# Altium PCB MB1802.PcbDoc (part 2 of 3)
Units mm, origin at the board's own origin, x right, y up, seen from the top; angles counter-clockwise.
Board outline 70 x 70 mm, 4 copper layers (Top Layer, Signal Layer 1, Signal Layer 2, Bottom Layer), stack 1.56 mm thick; 220 components, 159 nets, 974 pads, 563 vias.
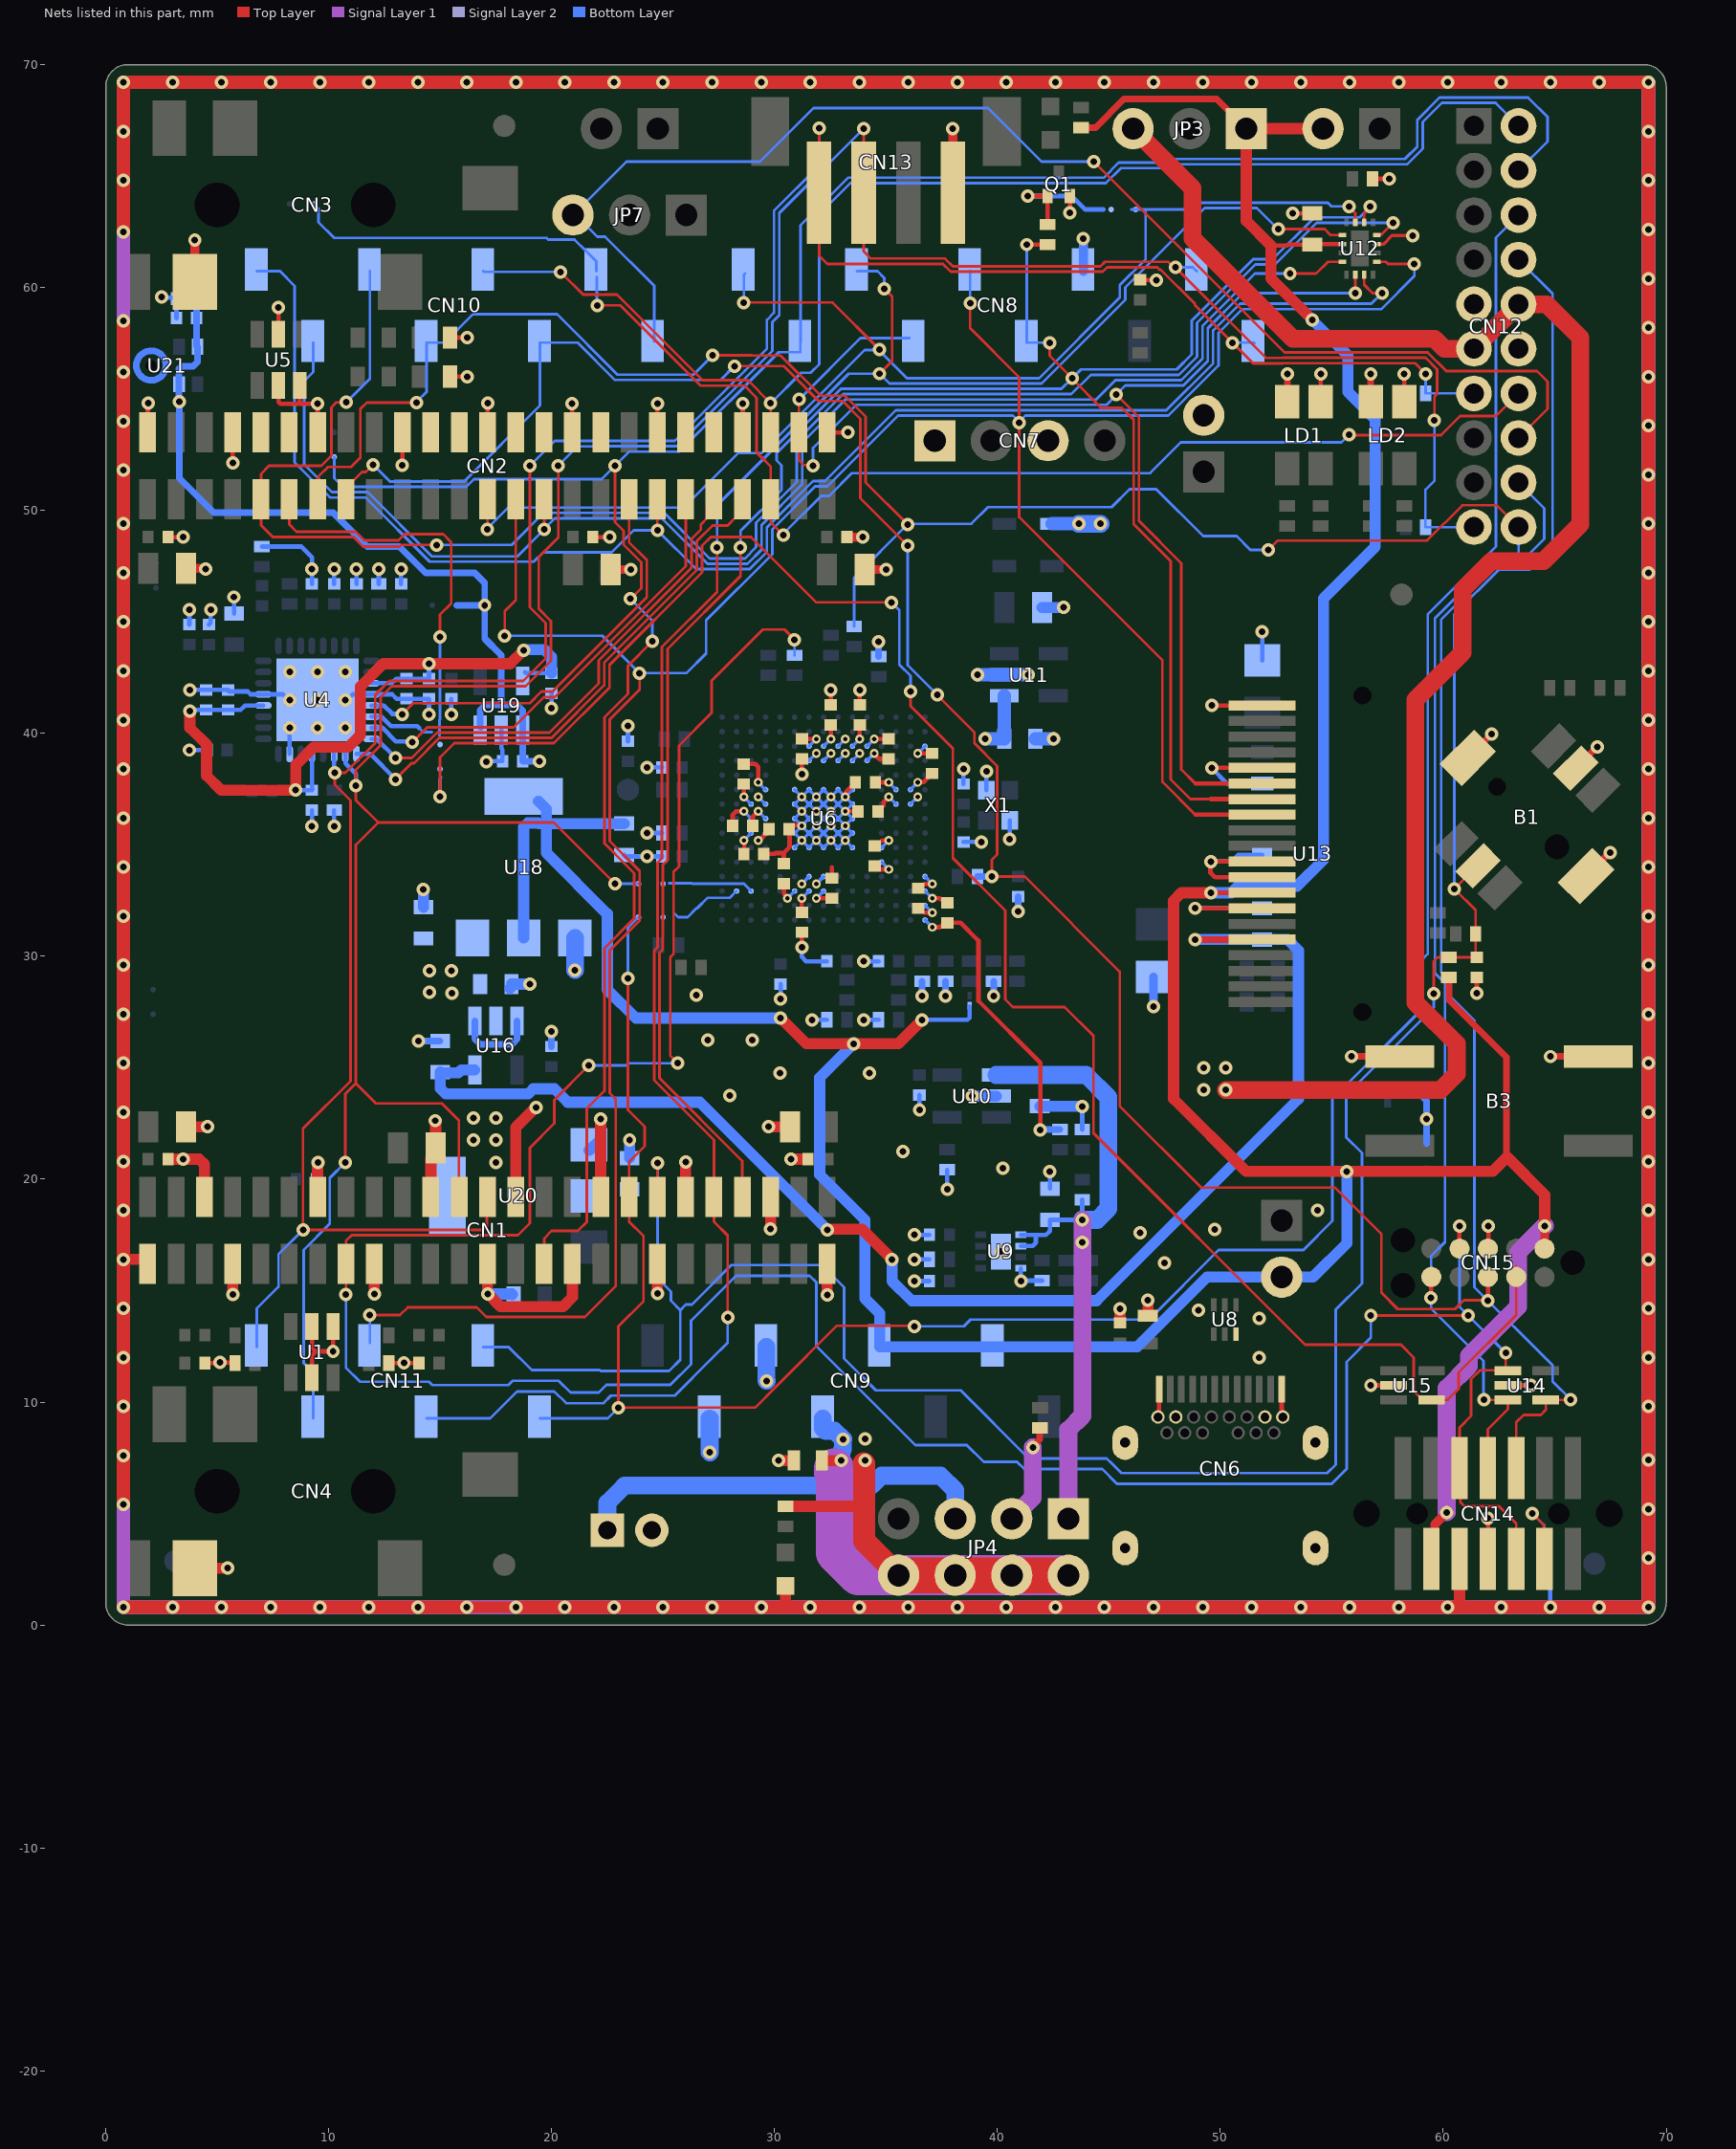
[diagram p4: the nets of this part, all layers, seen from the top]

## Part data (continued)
R48: library part MCD-00499, "Resistor,620R,0402,1%,1/16W", Manufacturer=YAGEO, Manufacturer_Part_Number=RC0402FR-07620RL, Package=R0402
R51 R52: library part MCD-00564, "Resistor,49R9,0603,1%,1/10W", Manufacturer=YAGEO, Manufacturer_Part_Number=RC0603FR-0749R9L, Package=R0603
R54: library part MCD-00057, "Resistor,2K2,0402,1%,1/16W", Manufacturer=YAGEO, Manufacturer_Part_Number=RC0402FR-072K2L, Package=R0402
R56: library part MCD-00419, "Resistor, 2K, 0402, +/-1%, 1/16W", Alternate_Manufacturer=N/A, Manufacturer=YAGEO, Manufacturer_Part_Number=RC0402FR-072KL, Package=0402
SB1 SB2 SB3 SB4 SB5 SB6 SB7 SB9 SB10: library part MCD-00071, "Solder Bridge ON"
SB8: library part MCD-00071, "Solder Bridge ON", Manufacturer=YAGEO, Manufacturer_Part_Number=RC0603JR-070RL, Package=SB0603
TP1: library part MCD-00074, "Test Point 1mm", Manufacturer=N/A
TP2: library part MCD-00630, "Test Point 0.3mm"
U1 U5: library part MCD-00247, "Quad Bidir ESD protection", Manufacturer=STMICROELECTRONICS, Manufacturer_HQ_COO=EU
U3: library part MCD-00170, "ESD protection 6V1", Manufacturer=STMICROELECTRONICS, Manufacturer_Part_Number=ESDALC6V1-1U2
U4: library part MCD-00265, "Low-Power, Stereo Codec with Headphone Amp", Manufacturer="CIRRUS LOGIC"
U6: library part MCD-02706, "MCU, Arm Cortex-M7 32-bit MCU, 512KB Flash, 276KB RAM, With Crypto", Manufacturer=STMICROELECTRONICS, Manufacturer_Part_Number=STM32F723IEK6, Package=BGA176
U7: library part MCD-01207, "High power Transient voltage suppressor:25V/35A EOS and ESD transients protection.", Manufacturer=STMICROELECTRONICS, Manufacturer_HQ_COO=EU, Manufacturer_Part_Number=ESDA25P35-1U1M, Package=QFN1610
U8: library part MCD-00649, "Common mode filter with ESD protection for USB 2.0 interface", Manufacturer=STMICROELECTRONICS, Manufacturer_HQ_COO=EU, Manufacturer_Part_Number=ECMF02-2AMX6
U9: library part MCD-02532, "IC, eFuse with Fast Overvoltage Protection 2.7V to 18V 4A 34mOhm 8-Pin WSON", Manufacturer="TEXAS INSTRUMENTS", Package=WSON8
U10: library part MCD-00159, "500mA, Enhanced single channel power switches with active high enable pin", Alternate_Manufacturer="TEXAS INSTRUMENTS", Alternate_Manufacturer_Part_Number=TPS2051C, Manufacturer=STMICROELECTRONICS
U11: library part MCD-02514, "LDO, 3.3V, 300mA, High input voltage: 2.5V to 28V, SOT23-5L", Manufacturer=STMICROELECTRONICS, Package=SOT23-5L
U12: library part MCD-00317, "Low voltage high bandwidth quad SPDT switch", Manufacturer=STMICROELECTRONICS
U13: library part MCD-01925, "128*64 Dots 20-pin OLED display", Manufacturer=RITDISPLAY, Manufacturer_Part_Number=9OL9935718000, Package=SMT
U14 U15: library part MCD-00136, "Dual Transil array for ESD protection", Manufacturer=STMICROELECTRONICS, Manufacturer_HQ_COO=EU
U16: library part MCD-01030, "LDO VOLTAGE REGULATOR, 3.6V, 150mA, 5-SOT-23, FULL REEL", Manufacturer="TEXAS INSTRUMENTS", Package=REG_SOT23-5L
U17: library part MCD-01026, "High power transient voltage suppressor", Manufacturer=STMICROELECTRONICS, Manufacturer_Part_Number=ESDA7P120-1U1M, Package=QFN1610
U18: library part MCD-00089, "LOW DROP FIXED AND ADJUSTABLE POSITIVE VOLTAGE REGULATORS (3.3 Volts)", Manufacturer=STMICROELECTRONICS
U19: library part MCD-00078, "Ultra low drop-low noise BiCMOS voltage, regulators low ESR capacitors compatible", Manufacturer=STMICROELECTRONICS
U20: library part MCD-00088, "IC REG LDO 5V 0.8A SOT223", Manufacturer=STMICROELECTRONICS
U21: library part MCD-02122, "MEMS sensors , omnidirectionnal digital microphone", Alternate_Manufacturer=N/A, Manufacturer=STMICROELECTRONICS, Manufacturer_Part_Number=MP23DB01HPTR, Package="RHLGA 5"
X1: library part MCD-01036, "Crystal, 24MHz, 6pF, +/-20ppm, 80R, 2x1.6mm", Manufacturer=NDK, Manufacturer_Part_Number=NX2016SA-24MHZ-EXS00A-CS10820, Package=2x1.6mm

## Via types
v1: diameter 0.6, hole 0.3, Top Layer to Bottom Layer, 509 vias
v2: diameter 0.4, hole 0.2, Top Layer to Bottom Layer, tented both sides, 54 vias

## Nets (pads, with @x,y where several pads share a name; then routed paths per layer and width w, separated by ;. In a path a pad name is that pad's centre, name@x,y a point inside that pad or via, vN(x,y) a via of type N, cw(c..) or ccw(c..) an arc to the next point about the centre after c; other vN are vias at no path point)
1V8: C16.2 C17.2 C18.2 C19.2 C20.2 C86.2 TP2.1 U4.5 U4.12 U4.27 U19.5 | length 34.6
  Top Layer w0.5: v1(3.775,40.99) 3.775,40.25 4.525,39.5 4.525,38.102 5.177,37.45 v1(8.525,37.45) 8.525,38.575 9.325,39.375 10.875,39.375 11.415,39.915 11.415,39.967 11.42,39.972 11.42,42.095 12.45,43.125 v1(14.5,43.125) 18.15,43.125 v1(18.75,43.725)
  Bottom Layer w0.2: v1(3.775,40.99) 3.835,41.05 C18.2@4.5,41.05 C19.2@5.5,41.05 6.05,41.05 6.25,41.25 U4.12@7.075,41.25 ; v1(8.525,37.45) C20.2@9.25,37.45 ; U4.5@9.255,39.125 9.255,37.52 C20.2@9.275,37.5 ; U4.27@11.925,42.25 12.825,42.25 13.025,42.45 C17.2@13.5,42.45 14.475,42.45 14.5,42.475 v1(14.5,43.125) ; U19.5@18.8,42.75 18.85,42.7 C86.2@20,42.7
  Bottom Layer w0.5: TP2.1@18.75,43.75 19.675,43.75 20,43.425 C86.2@20,42.7
3V3: C33.2 C34.1 C70.2 C74.1 C80.2 C85.2 CN9.2 CN9.4 CN14.3 CN15.1 JP2.2 JP3.1 JP5.2 LNK1.1 R41.1 R56.1 SB8.1 U12.2 U13.8 U18.2 U18.4 U19.1 U19.3 U21.2 U21.5 | length 233.6
  Top Layer w0.2: v1(49.575,32.85) U13.8@51.875,32.85 ; 52.26,61.89 52.275,61.875 53,61.875 53.05,61.925 C70.2@54.125,61.925 ; C70.2@54.125,61.95 U12.2@55.475,61.95
  Top Layer w0.3: R41.1@43.75,67.175 44.4,67.175 45.675,68.45 49.84,68.45 JP3.1@51.165,67.125 ; R56.1@60.25,29.05 60.25,28.05 62.825,25.475 62.825,21.025
  Top Layer w0.4: CN14.3@59.46,2.968 59.613,3.121 59.613,4.513 v1(60.15,5.05) ; CN15.1@64.54,16.885 64.55,16.895 v1(64.55,17.9)
  Top Layer w0.5: v1@30.294,27.206 31.425,26.075 v1(33.55,26.075) 35.55,26.075 v1(36.625,27.15) v1@36.65,27.175 ; v1(49.575,32.85) 48.25,32.85 47.9,32.5 47.9,23.6 51.15,20.35 62.22,20.35 62.86,20.99 64.55,19.3 v1(64.55,17.9) ; v1(54.125,58.545) 52.26,60.41 52.26,61.89 51.165,62.985 JP3.1@51.165,67.125 JP2.2@54.605,67.125
  Signal Layer 1 w0.8: v1(60.15,5.05) 60.15,10.625 61.15,11.625 61.15,12.075 63.35,14.275 63.35,16.7 v1(64.55,17.9)
  Bottom Layer w0.2: v1(36.625,27.15) 38.656,27.15 38.75,27.244 LNK1.1@38.75,27.75
  Bottom Layer w0.3: C33.2@4.075,59.5 C34.1@4.075,58.625 4.075,57.377 U21.5@4.114,57.338 4.114,56.664 3.925,56.475 3.415,56.475 3.292,56.352 U21.2@3.292,55.662 3.292,54.883 v1(3.3,54.875) 3.3,51.45 4.85,49.9 10.2,49.9 11.725,48.375 13.175,48.375 14.35,47.2 16.55,47.2 17,46.75 v1(17,45.75) ; SB8.1@15.75,45.75 v1(17,45.75) ; U19.3@16.825,40.275 16.8,40.3 16.8,41.05 17.025,41.275 17.738,41.275 ; U19.1@18.675,39.9 18.7,39.875 C85.2@18.7,38.75 v1(19.45,38.75) ; U19.1@18.7,40.15 18.7,41.025 18.45,41.275 17.738,41.275 ; v1(17,45.75) 17,44.25 17.738,43.512 17.738,41.275
  Bottom Layer w0.5: U18.2@18.75,30.825 18.75,35.798 18.932,35.98 19.383,35.98 19.413,35.95 19.763,35.95 ; U18.4@19.413,36.95 19.763,36.6 19.763,35.95 ; C80.2@23.25,35.95 19.763,35.95 ; v1(30.275,27.225) 23.775,27.225 22.5,28.5 22.5,31.9 19.763,34.637 19.763,35.95 ; v1(33.55,26.075) 32.025,24.55 32.025,20.2 34.05,18.175 34.05,14.65 34.725,13.975 34.714,13.964 34.714,12.472 39.794,12.472 46.272,12.472 49.405,15.605 JP5.2@52.75,15.605 54.155,15.605 55.675,17.125 v1(55.675,20.35) ; v1(49.575,32.85) 50.5,32.85 50.8,33.15 C74.1@51.875,33.15 53.45,33.15 54.625,34.325 54.625,46.05 56.95,48.375 56.95,54.1 55.725,55.325 55.725,56.945 v1@54.144,58.526
3V3_STLK: C50.1 C51.1 C52.1 C53.1 C54.1 C55.1 C56.1 C57.1 C58.1 C60.2 C61.1 C62.1 C63.1 C64.1 C65.1 C66.1 C67.1 C68.1 CN7.1 LD1.4 LD2.4 R28.2 R39.1 U6.C1 U6.C5 U6.C6 U6.C7 U6.C8 U6.C9 U6.F3 U6.G3 U6.G13 U6.H13 U6.J12 U6.J13 U6.K4 U6.N8 U6.N9 U6.N10 U6.P1 U6.R1 U11.1 | length 37.9
  Top Layer w0.2: C55.1@28.125,35.85 28.125,36.35 28.275,36.5 v2@28.6,36.5 ; v2(28.625,35.2) 28.65,35.175 C54.1@28.65,34.75 ; C56.1@28.625,37.725 28.625,37.175 v2@28.65,37.15 ; v2@29.275,35.225 29.35,35.225 29.595,35.47 29.62,35.47 29.775,35.625 C51.1@29.775,35.65 ; C53.1@30.425,33.225 30.425,32.786 30.575,32.636 v2(30.575,32.6) ; C52.1@31.225,31.975 31.225,32.45 v2@31.325,32.55 ; C57.1@31.225,39.75 31.825,39.75 v2@31.85,39.775 ; v2(31.875,32.6) C50.1@32.575,32.6 ; C58.1@32.525,40.375 32.525,39.775 v2@32.55,39.75 ; C61.1@33.825,40.375 33.825,39.725 v2@33.85,39.7 ; v2(34.475,39.75) 35.025,39.75 C62.1@35.1,39.825 ; C63.1@34.525,37.8 34.95,37.8 v2@35.05,37.7 ; C65.1@34.55,34.95 34.575,34.95 34.73,35.105 34.73,35.106 34.824,35.2 v2(35.125,35.2) ; C64.1@34.65,36.5 34.65,36.525 34.889,36.764 34.889,36.914 v2(35.125,37.15) ; v2@36.475,39.075 36.5,39.1 C68.1@37.075,39.1 ; C66.1@36.5,32.15 36.525,32.15 36.725,31.95 v2@37.025,31.95 ; v2(37.075,31.3) 37.425,31.3 37.625,31.5 37.65,31.5 38.35,31.5 39.15,30.7 39.15,28 41.925,25.225 v1(41.925,22.2)
  Top Layer w0.3: LD1.4@53,54.875 v1(53,56.125) ; LD2.4@56.75,54.875 v1(56.75,56.125)
  Bottom Layer w0.15: v2(28.625,35.2) U6.J13@28.95,35.525 ; v2(28.625,36.5) U6.H13@28.95,36.175 ; v2(28.625,37.15) U6.G13@28.95,36.825 ; v2(29.275,35.2) U6.J12@29.6,35.525 ; v2(30.575,32.6) U6.N10@30.9,32.925 ; v2(31.225,32.6) U6.N9@31.55,32.925 ; U6.C9@31.55,39.425 v2(31.875,39.75) ; v2(31.875,32.6) U6.N8@32.2,32.925 ; U6.C8@32.2,39.425 v2(32.525,39.75) ; U6.C7@32.85,39.425 v2(33.175,39.75) ; U6.C6@33.5,39.425 v2(33.825,39.75) ; U6.C5@34.15,39.425 v2(34.475,39.75) ; U6.K4@34.8,34.875 v2(35.125,35.2) ; v2(35.125,37.15) U6.G3@35.45,36.825 ; v2(35.125,37.8) U6.F3@35.45,37.475 ; v2(36.425,39.1) U6.C1@36.75,39.425 ; U6.R1@36.75,31.625 v2(37.075,31.3) ; U6.P1@36.75,32.275 v2(37.075,31.95)
  Bottom Layer w0.3: R28.2@34.675,43.45 v1(34.675,44.105) ; v1(41.925,22.2) 41.95,22.225 R39.1@42.8,22.225
  Bottom Layer w0.6: v1(39.45,39.75) C60.2@40.305,39.75 ; C60.2@40.275,39.775 40.305,39.805 U11.1@40.305,41.675
3V6: C75.1 C77.1 U13.5 U16.5 | length 63.8
  Top Layer w0.3: v1(48.875,30.75) U13.5@51.875,30.75
  Top Layer w0.5: v1(32.375,17.725) 32.4,17.75 33.925,17.75 v1(35.275,16.4)
  Bottom Layer w0.5: U16.5@16.55,24.9 15.95,24.9 15.825,24.775 15.025,24.775 C77.1@15,24.8 15,24.075 15.25,23.825 18.952,23.825 19.177,24.05 20.125,24.05 20.725,23.45 26.65,23.45 v1(32.375,17.725) ; v1(35.275,16.4) 35.275,15.425 36.15,14.55 44.45,14.55 53.5,23.6 53.5,30.268 53.018,30.75 C75.1@51.875,30.75 v1(48.875,30.75)
5V: C78.1 C81.2 CN9.5 CN12.6 CN12.15 JP3.3 JP4.2 JP4.4 JP4.6 JP4.8 R22.2 R48.2 U16.1 U16.3 U17.1 U18.3 | length 116.2
  Top Layer w0.5: R48.2@30.5,5.325 33.965,5.325 34.02,5.27 ; U17.1@32.125,7.375 v1(33,7.375)
  Top Layer w0.8: JP3.3@46.085,67.125 48.75,64.46 48.75,62.2 53.25,57.7 59.6,57.7 60.05,57.25 CN12.6@61.375,57.25 CN12.15@63.375,59.25 64.65,59.25 66.15,57.75 66.15,49.375 64.5,47.725 62.15,47.725 60.875,46.45 60.875,43.625 58.75,41.5 58.75,27.925 60.6,26.075 60.6,24.725 59.875,24 v1(50.25,24)
  Top Layer w1: v1@34,7.25 34.02,7.23 34.02,6.38 ; JP4.8@35.565,2.23 34.02,3.775 34.02,5.27 ; 34.02,5.27 34.025,5.275 34.025,6.375 34.02,6.38 ; 34.02,5.27 34.02,6.38
  Top Layer w1.6: JP4.8@35.565,2.23 JP4.6@38.105,2.23 JP4.4@40.645,2.23 JP4.2@43.185,2.23
  Signal Layer 1 w1.8: 32.68,7.03 32.68,6.845 32.75,6.775 32.75,3.25 33.77,2.23 JP4.8@35.52,2.23 ; JP4.8@35.5,2.25 JP4.8@35.52,2.23 ; JP4.6@38,2.25 JP4.6@38.02,2.23 ; JP4.4@40.645,2.23 JP4.6@38.105,2.23 JP4.6@38.02,2.23 ; JP4.4@40.75,2.25 40.75,2.24 40.76,2.23 JP4.2@43.185,2.23 ; JP4.8@35.52,2.23 JP4.8@35.565,2.23 JP4.6@38.02,2.23
  Bottom Layer w0.3: U16.1@16.55,27.1 16.55,26.3 16.8,26.05 18.225,26.05 18.45,26.275 U16.3@18.45,27.1 ; v1(36.625,28.22) R22.2@36.625,28.875
  Bottom Layer w0.8: CN9.5@32.174,9.267 32.174,8.824 32.284,8.714 32.686,8.714 33.068,8.332 v1(33.084,8.332) ; v1(33,7.375) 33,7.813 33.075,7.888 v1@33.075,8.325
  other v1: 34.075,7.375 34.075,8.35 49.25,24 49.25,25 50.25,25 15.525,28.35 14.525,28.375 14.525,29.35 15.5,29.35
5V_EXT: CN16.1 JP4.5 | length 19.1
  Bottom Layer w0.8: CN16.1@22.45,4.25 22.45,4.075 CN16.1@22.475,4.05 ; CN16.1@22.5,4.25 22.5,5.475 23.275,6.25 34.35,6.25 34.8,6.7 37.45,6.7 38.105,6.045 JP4.5@38.105,4.77
5V_STLK: C43.2 C47.2 JP4.1 R29.1 U9.5 U9.6 U10.1 | length 30.7
  Signal Layer 1 w0.8: JP4.1@43.185,4.77 43.185,8.76 43.819,9.394 43.819,17.272 v1@43.819,18.175
  Bottom Layer w0.2: U9.6@41.05,17 41.575,17 41.725,17.15 41.725,17.5 ; U9.5@41.05,17.5 41.725,17.5 ; C43.2@42.35,18.175 42.35,17.675 42.175,17.5 41.725,17.5 ; C43.2@42.355,18.175 v1(43.8,18.175) ; v1@43.805,18.28 R29.1@43.805,19.075
  Bottom Layer w0.8: U10.1@39.95,24.675 C47.2@41.9,24.675 43.975,24.675 44.975,23.675 44.975,18.675 44.475,18.175 v1(43.8,18.175)
  other v1: 43.8,17.175
5V_VIN: C84.2 D2.1 JP4.3 R43.2 U20.2 U20.4 | length 6.7
  Top Layer w0.3: v1(41.586,7.968) 41.586,8.011 41.9,8.325 R43.2@41.9,8.817
  Signal Layer 1 w0.8: JP4.3@40.645,4.77 41.586,5.711 v1(41.586,7.968)
  Bottom Layer w0.6: D2.1@42.445,49.4 v1(43.65,49.4)
  Bottom Layer w0.8: v1(43.65,49.4) v1(44.625,49.4)
  other v1: 17.5,20.75 16.5,21.75 17.5,21.75 16.5,22.75 17.5,22.75
ARD.D0_RX: CN2.37 CN10.1 U12.7 | length 71.3
  Top Layer w0.12: v1(24.745,49.105) CN2.37@24.745,50.5 ; U12.7@56.45,60.575 56.45,60.125 56.825,59.75 v1(57.25,59.75)
  Bottom Layer w0.12: CN10.1@6.774,60.73 7.82,60.73 8.475,60.075 8.475,52.15 9.805,50.82 9.816,50.82 10.056,50.58 11.656,50.58 14.536,47.7 19.2,47.7 19.625,48.125 22.7,48.125 23.68,49.105 v1(24.745,49.105) 26.485,47.365 28.886,47.365 29.66,48.139 29.66,49.249 31.726,51.315 32.265,51.315 35.445,54.495 47.57,54.495 49.675,56.6 49.675,58.071 50.879,59.275 55.846,59.275 55.851,59.27 56.77,59.27 v1(57.25,59.75)
ARD.D1_TX: CN2.29 CN10.2 U12.4 | length 65
  Top Layer w0.12: CN2.29@19.665,50.5 19.665,49.16 v1(19.675,49.15) ; v1(53.125,60.625) 54.3,60.625 54.825,61.15 U12.4@55.475,61.15
  Bottom Layer w0.12: CN10.2@9.314,57.525 9.314,56.211 8.9,55.797 8.9,52.075 10.15,50.825 10.536,50.825 10.541,50.82 11.755,50.82 14.635,47.94 18.465,47.94 v1(19.675,49.15) ; v1@19.675,49.175 20.15,49.65 24.95,49.65 26.995,47.605 28.787,47.605 29.42,48.238 29.42,49.349 31.24,51.169 31.24,53.032 33.183,54.975 44.425,54.975 45.295,55.845 48.241,55.845 49.195,56.799 49.195,58.27 51.55,60.625 v1(53.125,60.625)
ARD.D2_IO: CN2.9 CN10.3 U12.12 | length 77.5
  Top Layer w0.12: v1@10.775,54.85 10.35,54.85 10.125,54.625 10.125,52.45 9.675,52 7.325,52 6.965,51.64 CN2.9@6.965,50.5 6.965,49.335 7.495,48.805 11.12,48.805 11.548,48.378 13.192,48.378 13.264,48.45 v1(14.85,48.45) ; U12.12@57.025,62.35 57.065,62.39 57.24,62.39 v1(57.75,62.9)
  Bottom Layer w0.12: v1(10.8,54.85) 11.854,55.904 CN10.3@11.854,60.73 ; v1(14.85,48.45) 18.2,48.45 19.625,49.875 ; 19.625,49.89 25.049,49.89 27.094,47.845 28.674,47.845 29.18,48.351 29.18,49.448 31,51.268 31,53.132 33.083,55.215 43.315,55.215 44.185,56.085 48.142,56.085 48.955,56.898 48.955,58.417 51.573,61.035 52.449,61.035 54.314,62.9 v1(57.75,62.9)
ARD.D3_TIM: CN2.13 CN10.4 CN12.20 CN14.8 CN15.6 R17.2 U14.3 | length 123.5
  Top Layer w0.12: CN2.13@9.505,50.5 9.55,50.545 9.55,51.525 9.975,51.95 11,51.95 11.425,52.375 11.425,54.55 11.715,54.84 v1(13.95,54.84) ; v1(27.225,56.955) 28.975,56.955 ; 28.975,56.95 30.275,56.95 32.075,55.15 33.15,55.15 34.09,54.21 34.09,51.26 v1(35.975,49.375) ; v1(52.15,48.225) 52.575,48.65 59.275,48.65 60.855,50.23 62.395,50.23 CN12.20@63.375,49.25 ; v1(61.825,10.1) U14.3@62.9,10.1 62.9,9.675 62,8.775 CN14.8@62,7.032
  Top Layer w0.2: v1(59.45,14.675) 59.46,14.685 CN15.6@59.46,15.6
  Bottom Layer w0.12: v1@13.95,54.875 14.394,55.319 14.394,57.525 15.2,57.525 16.475,58.8 20.25,58.8 22.96,56.09 26.36,56.09 v1@27.22,56.95 ; R17.2@33.575,44.8 33.575,46.975 v1@36,49.4 ; v1(35.975,49.375) v1@36,49.4 ; v1(52.15,48.225) 51.346,48.225 50.726,48.845 49.226,48.845 47.116,50.955 45.93,50.955 45.125,50.15 39.575,50.15 38.825,49.4 v1@36,49.4 ; v1@61.8,10.1 61.8,11.85 59.45,14.2 v1(59.45,14.675) 59.45,16.55 60.075,17.175 60.075,28.8 59.625,29.25 59.625,45.154 62.301,47.83 63.13,47.83 63.375,48.075 CN12.20@63.375,49.25
ARD.D4_INT: CN2.46 CN10.5 CN12.11 | length 60.9
  Top Layer w0.12: v1@20.45,60.65 21.42,59.68 22.249,59.68 22.254,59.675 22.35,59.675 22.355,59.68 22.934,59.68 26.774,55.84 28.805,55.84 v1(29.825,54.82) 29.825,53.55 CN2.46@29.75,53.475
  Bottom Layer w0.12: CN10.5@16.934,60.73 16.964,60.7 v1(20.4,60.7) ; v1@29.825,54.8 31.2,56.175 31.625,56.175 32,56.55 32,63.286 33.399,64.684 44.863,64.684 45.538,65.359 47.334,65.359 47.5,65.525 58.375,65.525 59.075,66.225 59.075,67.425 59.93,68.28 62.345,68.28 CN12.11@63.375,67.25
ARD.D5_TIM: CN2.15 CN10.6 CN12.19 CN14.10 CN15.8 R19.2 U14.4 | length 142.6
  Top Layer w0.12: CN2.15@10.775,50.5 10.775,51.025 11.09,51.34 11.115,51.34 11.5,51.725 11.675,51.725 v1(12,52.05) ; v1(28.2,56.475) 30.411,56.475 30.818,56.068 31.976,54.91 33.051,54.91 33.85,54.111 33.85,50.54 v1(35.975,48.415) ; v1(37.3,41.725) 37.275,41.725 38.97,40.03 38.97,39.551 39.985,38.536 39.985,34.56 39.745,34.32 39.745,33.58 39.75,33.575 v1(39.755,33.575) 41.225,33.575 45.485,29.315 45.485,23.276 49.136,19.625 55.125,19.625 57.225,17.525 57.225,14.9 57.95,14.175 60.525,14.175 60.925,14.575 61.975,14.575 v1(62,14.55) ; CN14.10@63.27,7.032 63.27,9.095 63.6,9.425 64.375,9.425 64.6,9.65 U14.4@64.6,10.075 ; U14.4@64.6,10.1 v1(65.7,10.1)
  Top Layer w0.2: v1(62,14.55) CN15.8@62,15.615
  Bottom Layer w0.12: v1(12,52.05) 12.75,51.3 16.075,51.3 19.475,54.7 19.475,55.85 19.474,57.525 21.175,57.525 22.85,55.85 27.575,55.85 v1(28.2,56.475) ; v1(35.975,48.415) 35.975,43.05 v1(37.3,41.725) ; CN12.19@63.375,51.25 64.525,50.1 64.525,48.725 63.39,47.59 62.401,47.59 59.9,45.089 59.9,29.314 60.315,28.899 60.315,28.199 61.4,27.114 61.4,15.15 64.9,11.65 64.9,10.925 v1@65.7,10.125
  Bottom Layer w0.3: R19.2@39.1,33.575 v1(39.755,33.575)
ARD.D6_TIM: CN2.45 CN10.7 CN12.17 SB3.2 | length 67
  Top Layer w0.12: v1(22.05,59.2) 23.075,59.2 26.675,55.6 28.65,55.6 29.2,55.05 29.2,52.6 29.27,52.53 29.27,52.525 29.375,52.42 29.38,52.42 29.825,51.975 29.825,49.475 v1(30.4,48.9) ; v1(55.764,53.389) 55.779,53.375 59.9,53.375 60.755,54.23 62.355,54.23 CN12.17@63.375,55.25
  Bottom Layer w0.12: SB3.2@9.35,63.75 9.55,63.55 9.55,62.925 10.25,62.225 19.775,62.225 19.85,62.15 20.497,62.15 20.502,62.145 21.03,62.145 21.552,61.623 21.564,61.623 22.014,61.173 CN10.7@22.014,60.73 ; CN10.7@22.025,60.475 22.025,59.225 v1(22.05,59.2) ; v1(30.4,48.9) 30.4,48.95 32.1,50.65 32.45,50.65 33.475,51.675 46.85,51.675 48.225,53.05 55.425,53.05 v1(55.764,53.389)
ARD.D7_IO: CN10.8 CN12.18 JP7.3 | length 61.3
  Top Layer w0.12: v1(44.325,65.644) 52.879,57.09 59.299,57.09 60.139,56.25 64.2,56.25 64.675,55.775 64.675,54.55 CN12.18@63.375,53.25
  Bottom Layer w0.12: CN10.8@24.6,57.575 24.6,60.078 22.403,62.275 22.048,62.275 21.073,63.25 JP7.3@20.96,63.25 23.36,65.65 29.35,65.65 31.75,68.05 39.575,68.05 41.981,65.644 v1(44.325,65.644)
ARD.D8_IO: CN2.25 CN8.1 SB2.1 U12.15 | length 58.6
  Top Layer w0.12: v1(17.125,49.15) CN2.25@17.125,50.5 ; v1(28.625,59.325) 32.6,59.325 v1(34.7,57.225) ; v1(55.764,63.639) 55.764,63.611 56.05,63.325 U12.15@56.05,62.925
  Bottom Layer w0.12: v1(17.125,49.15) 17.125,49.2 18.055,50.13 25.93,50.13 28.375,52.575 29.425,52.575 34.05,57.2 v1@34.675,57.2 ; v1(28.625,59.325) 28.625,60.575 CN8.1@28.675,60.625 ; v1@34.7,57.175 35.94,55.935 41.875,55.935 45.49,59.55 45.49,60.104 46.65,61.264 46.65,63.5 ; 46,63.5 SB2.1@46.2,63.5 46.65,63.5 ; v1(55.764,63.639) 54.986,63.639 54.82,63.805 48.7,63.805 48.395,63.5 46.65,63.5
ARD.D9_TIM: CN1.29 CN8.2 CN12.12 SB4.2 | length 110.8
  Top Layer w0.12: CN1.29@19.665,16.21 19.665,17.34 20,17.675 21.175,17.675 21.575,18.075 21.575,23.164 22.37,23.959 22.37,30.359 23.71,31.699 23.71,33.726 23.38,34.055 22.37,35.066 22.37,40.724 23.425,41.779 23.425,43.025 v1(24.525,44.125) ; v1(22.85,52) 22.85,49.475 23.235,49.09 23.235,48.465 24.03,47.67 24.03,46.505 23.566,46.041 v1(23.534,46.041)
  Bottom Layer w0.12: SB4.2@10.25,52.4 10.25,51.45 10.64,51.06 16.174,51.06 16.514,51.4 22.25,51.4 v1(22.85,52) 23.49,52.64 25.731,52.64 30.191,57.1 CN8.2@31.15,57.1 ; v1(23.534,46.041) 24.525,45.05 v1(24.525,44.125) ; CN8.2@31.158,57.1 CN8.2@31.158,57.525 ; CN8.2@31.175,57.55 31.175,62.8 33.299,64.924 44.764,64.924 45.439,65.599 47.235,65.599 47.401,65.765 58.276,65.765 58.835,66.324 58.835,67.524 59.831,68.52 63.805,68.52 64.675,67.65 64.675,66.55 CN12.12@63.375,65.25
ARD.D10_TIM_SPI3_NSS: CN1.42 CN8.3 CN11.3 U12.1 | length 96.2
  Top Layer w0.12: v1(27.425,48.325) 27.425,46.346 24.95,43.871 24.95,34.4 24.75,34.2 24.75,30.4 24.6,30.25 24.6,24.436 27.285,21.751 CN1.42@27.285,19.21 27.285,18.09 27.9,17.475 v1(27.9,13.8) ; v1(34.713,56.133) 35.275,56.695 35.275,59.6 v1(34.925,59.95) ; v1(52.593,62.625) 54.675,62.625 54.95,62.35 U12.1@55.475,62.35
  Bottom Layer w0.12: CN11.3@14.394,9.267 17.242,9.267 18.452,10.477 20.123,10.477 20.65,9.95 22.325,9.95 22.665,10.29 25.523,10.29 27.165,11.932 27.9,12.667 v1(27.9,13.8) ; v1(27.425,48.325) 27.425,50.236 33.322,56.133 34.717,56.133 35.155,55.695 41.974,55.695 45.73,59.451 45.73,60.005 49.29,63.565 51.635,63.565 52.575,62.625 v1(52.593,62.625) ; CN8.3@33.698,60.73 34.62,60.73 34.925,60.425 v1(34.925,59.95)
ARD.D11_TIM_SPI3_MOSI: CN2.48 CN8.4 U12.6 U13.15 | length 61
  Top Layer w0.12: v1@31.095,54.85 CN2.48@31.095,53.5 31.095,52.255 31.318,52.032 31.693,52.032 v1(31.725,52) ; v1@45.325,55.2 46.35,54.175 46.35,49.525 48.25,47.625 48.25,38.375 48.875,37.75 ; v1(56.05,59.75) U12.6@56.05,60.575
  Top Layer w0.2: 48.875,37.75 U13.15@51.875,37.75
  Bottom Layer w0.12: v1(31.1,54.975) 33.85,57.725 CN8.4@36.05,57.725 ; v1(31.725,52) 31.725,52.805 33.655,54.735 44.885,54.735 v1@45.35,55.2 ; v1@45.337,55.212 45.73,55.605 48.341,55.605 49.435,56.699 49.435,58.171 51.014,59.75 v1(56.05,59.75)
  other v1: 45.327,55.198
ARD.D12_SPI3_MISO: CN2.27 CN8.5 CN11.4 U12.9 U13.13 | length 134.1
  Top Layer w0.12: v1(11.85,13.9) 13.2,13.9 13.55,14.25 16.65,14.25 17.075,13.825 21.5,13.825 22.875,15.2 22.875,23.595 22.61,23.86 22.61,30.26 23.95,31.6 23.95,33.825 22.61,35.165 22.61,40.624 23.95,41.964 v1(23.95,42.7) ; v1(17.9,44.375) 17.9,45.475 18.395,45.97 CN2.27@18.395,50.5 ; v1(38.775,59.3) 38.775,58.175 40.975,55.975 v1(40.975,53.925) 40.975,49.7 47.4,43.275 47.4,37.825 48.875,36.35 ; U12.9@57.025,61.15 57.425,61.15 57.52,61.055 v1(58.7,61.055)
  Top Layer w0.2: 48.875,36.35 U13.13@51.875,36.35
  Bottom Layer w0.12: CN11.4@11.85,12.65 v1(11.85,13.9) ; v1(17.9,44.375) 22.275,44.375 v1(23.95,42.7) 26.046,42.7 26.93,43.584 26.93,45.069 29.9,48.039 29.9,49.15 31.825,51.075 32.364,51.075 35.544,54.255 40.69,54.255 v1@40.975,53.97 ; v1(38.775,59.3) 38.778,59.303 CN8.5@38.778,60.73 ; v1(40.975,53.925) v1@40.975,53.97 ; v1(58.7,61.055) 58.7,60.521 57.204,59.025 50.968,59.025 49.915,57.972 49.915,56.501 47.664,54.25 41.251,54.25 40.975,53.974 v1@40.975,53.97
ARD.D13_SPI3_SCK: CN1.44 CN8.6 R42.1 U12.14 U13.14 | length 103.3
  Top Layer w0.12: v1(28.475,48.325) 28.475,47.057 25.2,43.782 25.2,34.311 24.99,34.101 24.99,30.301 24.84,30.151 24.84,24.535 28.555,20.82 CN1.44@28.555,19.21 ; v1@42.35,57.55 v1(42.35,57.525) 42.35,56.935 v1(43.35,55.935) ; v1@43.35,55.9 44.65,54.6 45.586,54.6 46.11,54.076 46.11,49.39 47.775,47.725 47.775,37.925 48.65,37.05 49.575,37.05 ; U12.14@56.45,62.925 56.45,63.321 56.725,63.596 v1(56.725,63.625)
  Top Layer w0.2: v1(41.325,61.925) 42.1,61.925 R42.1@42.15,61.975 ; 49.575,37.05 U13.14@51.875,37.05
  Bottom Layer w0.12: v1(28.475,48.325) 28.475,49.083 30.305,50.913 30.305,52.03 30.1,52.235 30.1,52.571 32.984,55.455 42.87,55.455 v1(43.35,55.935) ; v1(41.325,61.925) 41.318,61.918 41.318,57.525 v1@42.35,57.525 ; v1@43.355,55.93 43.75,56.325 48.042,56.325 48.715,56.998 48.715,58.516 51.474,61.275 52.35,61.275 54.225,63.15 56.25,63.15 v1(56.725,63.625)
ARD_ADC.A0: CN1.36 CN11.1 CN12.13 SB10.2 | length 111.4
  Top Layer w0.12: v1(23.425,29) 23.425,23.1 24.175,22.35 24.175,21.475 23.475,20.775 CN1.36@23.475,19.21 23.475,18.1 24.125,17.45 24.125,14.525 23,13.4 v1(23,9.75) 29.129,9.75 30.13,10.751 30.13,10.755 32.8,13.425 36.25,13.425 v1(36.275,13.4)
  Bottom Layer w0.12: CN11.1@19.474,9.267 22.517,9.267 v1(23,9.75) ; v1(23.425,29) 23.425,31.275 SB10.2@23.9,31.75 ; v1(36.275,13.4) 38.496,13.4 38.796,13.7 46.8,13.7 49.925,16.825 53.725,16.825 55.025,18.125 55.025,23.6 59.025,27.6 59.025,29.825 59.3,30.1 59.3,45.325 62.355,48.38 62.355,62.23 CN12.13@63.375,63.25
ARD_ADC.A1: B1.2 C13.2 CN1.38 CN11.2 CN12.14 R4.1 R56.2 | length 119.8
  Top Layer w0.12: CN1.38@24.745,19.21 24.745,20.72 v1(24.75,20.725) ; v1(59.57,28.325) 59.57,29.77 59.75,29.95 R56.2@60.225,29.95 ; R56.2@60.25,29.95 C13.2@61.47,29.95 ; C13.2@61.5,29.95 61.45,30 R4.1@61.45,31 61.45,32.068 v1(60.5,33.018) B1.2@61.55,34.068
  Bottom Layer w0.12: CN11.2@16.934,12.472 18.075,12.472 19.11,11.437 22.164,11.437 22.211,11.39 25.265,11.39 25.775,11.9 25.775,14.125 ; v1(24.75,20.725) 24.75,15.554 25.35,14.954 25.35,14.55 25.775,14.125 ; v1@59.575,28.35 59.575,27.7 55.65,23.775 55.65,21.875 56.35,21.175 56.35,15.325 55.175,14.15 55.175,7.197 54.793,6.815 45.56,6.815 45.125,7.25 44.9,7.475 41.4,7.475 38.35,10.525 34.547,10.525 33.115,11.957 33.115,15.149 32.114,16.15 28.071,16.15 26.296,14.375 26.025,14.375 25.775,14.125 ; v1@60.5,33.05 60.5,45.35 62.5,47.35 63.875,47.35 64.9,48.375 64.9,59.725 CN12.14@63.375,61.25
ARD_ADC.A4: CN1.24 CN8.9 CN11.5 CN12.10 CN13.2 R9.1 SB5.2 U4.2 | length 143
  Top Layer w0.12: v1(10.75,20.75) 10.75,23.825 11.223,24.298 ; CN1.24@15.855,19.21 15.84,19.225 15.84,22.635 15.075,23.4 12.122,23.4 11.223,24.298 ; v1(20.3,52) 20.3,48.775 19.425,47.9 19.425,45.589 19.975,45.039 19.975,43.258 18.827,42.11 12.824,42.11 12.33,41.616 12.33,39.466 11.223,38.359 11.223,37 12.223,36 ; v1(22.85,33.25) 20.1,36 12.223,36 ; v1(34,67.125) CN13.2@34,64.25 34,61.625 34.325,61.3 37.65,61.3 38,60.95 44.625,60.95 44.825,61.15 47.667,61.15 47.915,60.902 v1(47.977,60.902) 52.034,56.845 52.8,56.845 ; 52.8,56.85 59.2,56.85 59.725,56.325 59.725,55.225 59.6,55.1 59.6,54.225 v1@59.575,54.2 ; 11.223,24.298 11.223,35 12.223,36
  Bottom Layer w0.12: CN11.5@9.314,9.267 9.314,11.311 8.875,11.75 8.875,16.825 10.05,18 10.05,20.05 v1(10.75,20.75) ; v1(20.3,52) 21.175,52.875 21.925,52.875 ; 21.925,52.88 25.623,52.88 29.9,57.157 29.9,58.45 30.215,58.765 30.215,63.34 v1(34,67.125) ; v1(22.85,33.25) SB5.2@23.9,33.25 ; v1(47.977,60.902) 48.767,60.902 CN8.9@48.938,60.73 ; v1(59.6,54.05) 59.6,51.325 59.2,50.925 R9.1@59.2,49.25 61.35,49.25 CN12.10@61.4,49.3
  Bottom Layer w0.2: U4.2@10.75,39.075 10.752,39.073 10.752,38.648 11.23,38.17 11.23,37.657 v1(11.223,37.65)
ARD_ADC.A5: CN1.26 CN8.10 CN11.6 CN12.7 CN13.1 R8.1 U4.3 | length 123.1
  Top Layer w0.12: CN1.26@17.125,19.21 17.1,19.185 17.1,17.875 16.95,17.725 v1(8.85,17.725) 8.85,22.264 10.983,24.398 10.983,36.992 10.275,37.7 v1(10.275,38.225) 10.75,38.225 12.09,39.565 12.09,41.715 12.725,42.35 18.728,42.35 19.735,43.357 19.735,44.94 19.025,45.65 v1(19.025,52) ; v1(32,67.15) CN13.1@32,64.25 32,61.425 32.365,61.06 37.551,61.06 37.901,60.71 44.724,60.71 44.914,60.9 47.175,60.9 47.27,60.805 47.324,60.805 48.859,59.27 48.859,59.216 51.475,56.6 52.796,56.6 52.801,56.605 58.73,56.605 v1(59.21,56.125)
  Bottom Layer w0.12: CN11.6@6.774,12.472 6.774,14.199 7.75,15.175 7.75,16.625 v1(8.85,17.725) ; v1(19.025,52) 20.15,53.125 20.8,53.125 ; 20.8,53.12 25.52,53.12 28.395,55.995 28.399,55.995 28.68,56.276 28.68,56.28 29.66,57.26 29.66,58.549 29.975,58.864 29.975,63.439 32,65.464 v1(32,67.15) ; v1(50.55,57.525) 51.5,57.525 CN8.10@51.525,57.5 ; v1(59.21,56.125) 59.21,55.26 R8.1@59.2,55.25 CN12.7@61.375,55.25
  Bottom Layer w0.2: U4.3@10.25,39.075 10.25,38.25 v1(10.275,38.225)
Audio.FS_B: CN2.43 U4.1 | length 24.6
  Top Layer w0.12: v1(13,37.94) 13.72,38.66 13.829,38.66 14.964,39.795 20.006,39.795 22.36,42.149 22.36,43.171 26.515,47.326 26.515,48.626 27.214,49.325 27.9,49.325 28.235,49.66 28.24,49.66 28.555,49.975 CN2.43@28.555,50.5
  Bottom Layer w0.2: U4.1@11.25,39.075 11.865,39.075 v1(13,37.94)
Audio.MCLK_B: CN2.11 SB9.1 U4.30 | length 20.8
  Top Layer w0.12: CN2.11@8.235,50.5 8.235,49.375 8.565,49.045 11.219,49.045 11.604,48.66 13.135,48.66 13.405,48.93 15.145,48.93 15.5,48.575 15.5,45.825 15,45.325 v1(15,44.325)
  Bottom Layer w0.12: 14.05,40.25 14.25,40.05 14.625,40.05 ; 14.975,39.9 14.975,40.6 15,40.625 v1(15,44.325)
  Bottom Layer w0.2: U4.30@11.925,40.75 12.365,40.75 12.79,40.325 13.975,40.325 14.05,40.25
Audio.SCK_B: CN2.39 U4.31 | length 20.6
  Top Layer w0.12: v1(13.758,39.608) 14.426,40.275 18.3,40.275 19.65,41.625 20.136,41.625 26.015,47.504 CN2.39@26.015,50.5
  Bottom Layer w0.2: U4.31@11.925,40.25 12.4,40.25 13.019,39.631 13.735,39.631 v1(13.758,39.608)
Audio.SD_A: CN2.35 U4.29 | length 19.4
  Top Layer w0.12: v1(13.3,40.85) 13.8,41.35 19.025,41.35 19.55,41.875 20.046,41.875 24.27,46.099 24.27,47.769 23.475,48.564 CN2.35@23.475,50.5
  Bottom Layer w0.2: U4.29@11.925,41.25 12.475,41.25 12.852,40.873 13.277,40.873 v1(13.3,40.85)
Audio.SD_B: CN2.41 U4.32 | length 22.3
  Top Layer w0.12: v1(13,38.9) 13.729,38.9 14.238,39.409 14.238,39.413 14.86,40.035 19.906,40.035 22.12,42.249 22.12,43.27 26.275,47.425 26.275,48.725 26.7,49.15 26.7,49.375 26.97,49.645 26.97,50.185 CN2.41@27.285,50.5
  Bottom Layer w0.2: U4.32@11.925,39.75 12.15,39.75 v1(13,38.9)
GND: B1.5 B1.7 B1.8 B3.3 B3.4 C1.2 C2.1 C3.1 C4.1 C5.1 C6.1 C7.1 C8.2 C9.1 C10.1 C11.1 C13.1 C14.1 C15.1 C16.1 C17.1 C18.1 C19.1 C20.1 C22.2 C24.1 C27.2 C28.1 C29.1 C30.1 C31.1 C32.1 C33.1 C34.2 C35.2 C36.1 C37.2 C38.2 C39.2 C40.1 C41.1 C42.1 C43.1 C44.1 C45.1 C46.1 C47.1 C48.1 C49.1 C50.2 C51.2 C52.2 C53.2 C54.2 C55.2 C56.2 C57.2 C58.2 C59.1 C60.1 C61.2 C62.2 C63.2 C64.2 C65.2 C66.2 C67.2 C68.2 C69.2 C70.1 C73.2 C74.2 C75.2 C76.2 C77.2 C78.2 C79.2 C80.1 C81.1 C82.1 C83.1 C84.1 C85.1 C86.1 C87.2 CN1.1 CN1.6 CN1.7 CN1.14 CN1.17 CN1.22 CN1.25 CN1.28 CN1.31 CN1.34 CN1.37 CN1.40 CN1.46 CN1.49 CN2.2 CN2.8 CN2.14 CN2.20 CN2.26 CN2.32 CN2.38 CN2.44 CN2.50 CN3.3 CN4.3 CN6.A1 CN6.A12 CN6.B1 CN6.B12 CN6.SH1 CN6.SH2 CN6.SH3 CN6.SH4 CN7.3 CN8.7 CN9.6 CN9.7 CN12.5 CN12.16 CN13.4 CN14.5 CN14.7 CN15.3 CN16.2 JP1.2 LD1.3 LD2.3 LD4.2 Q1.2 R7.2 R10.1 R11.2 R15.2 R23.2 R25.2 R27.2 R30.2 R33.2 R34.1 R40.1 R45.1 R46.1 R47.1 R49.2 R51.2 R52.2 R53.2 R55.2 SB1.2 U1.2 U1.4 U1.5 U3.2 U4.7 U4.13 U4.28 U4.33 U5.2 U5.3 U5.5 U6.D5 U6.D6 U6.D7 U6.D8 U6.D9 U6.F2 U6.F6 U6.F7 U6.F8 U6.F9 U6.F10 U6.F12 U6.G2 U6.G6 U6.G7 U6.G8 U6.G9 U6.G10 U6.G12 U6.H6 U6.H7 U6.H8 U6.H9 U6.H10 U6.H12 U6.J6 U6.J7 U6.J8 U6.J9 U6.J10 U6.K6 U6.K7 U6.K8 U6.K9 U6.K10 U6.L4 U6.M1 U6.M8 U6.M9 U6.N1 U7.2 U8.3 U9.8 U9.9 U10.2 U11.2 U12.11 U13.7 U13.9 U13.10 U13.16 U13.20 U14.2 U15.2 U16.2 U17.2 U18.1 U19.2 U20.1 U21.3 X1.2 X1.4 | length 1333.3
  Top Layer w0.15: U12.11@57.025,61.95 57.325,61.95 57.7,62.325 v1(58.625,62.325) v1@58.7,62.325
  Top Layer w0.2: CN2.2@1.885,53.5 1.889,53.504 1.889,54.809 v1(1.9,54.82) ; C9.1@2.8,48.8 v1(3.475,48.8) ; C87.2@4.45,11.75 5.1,11.75 v1(5.125,11.775) ; v1@5.175,11.725 5.214,11.764 5.786,11.764 R10.1@5.8,11.75 ; CN2.8@5.695,53.5 5.695,52.13 v1(5.7,52.125) ; U5.2@7.75,55.6 7.75,54.869 7.844,54.775 8.669,54.775 ; U5.5@7.75,57.9 v1(7.75,59.1) ; U5.3@8.7,55.6 8.7,54.806 8.669,54.775 ; U1.2@9.25,11.1 9.25,12.1 9.425,12.275 ; U1.5@9.25,13.4 9.25,12.425 9.4,12.275 9.425,12.275 ; v1@9.5,54.775 9.5,53.505 CN2.14@9.505,53.5 ; v1(9.5,54.8) 9.475,54.775 8.669,54.775 ; v1@10.2,12.225 10.15,12.275 9.425,12.275 ; v1(10.2,12.275) U1.4@10.2,13.4 ; R7.2@12.7,11.75 13.325,11.75 v1@13.4,11.825 ; v1(13.3,52.025) 13.315,52.04 CN2.20@13.315,53.5 ; v1(13.375,11.75) C14.1@14.05,11.75 ; R51.2@15.45,56 v1(16.225,56) ; R52.2@15.45,57.75 v1(16.225,57.75) ; CN2.26@17.125,53.504 v1@17.125,54.809 ; v1(20.925,54.8) 20.925,53.51 CN2.32@20.935,53.5 ; C10.1@21.85,48.8 v1(22.6,48.8) ; CN2.38@24.745,53.5 24.75,53.505 v1(24.75,54.8) ; CN2.44@28.555,53.5 28.572,53.517 v1(28.572,54.803) ; C56.2@28.625,38.625 29.15,38.625 29.275,38.5 29.275,37.85 v2@29.3,37.825 ; C55.2@29.025,35.85 29.025,36.264 29.275,36.514 v2@29.275,36.55 ; C54.2@29.625,34.6 30.025,34.6 30.05,34.625 30.419,34.625 ; C53.2@30.42,34.15 30.419,34.151 30.419,34.625 ; C52.2@31.225,31.075 31.225,30.45 v1@31.25,30.425 ; C57.2@31.225,38.85 31.225,38.4 v1@31.275,38.35 ; v2@31.275,35.875 30.9,35.875 30.855,35.83 30.83,35.83 30.675,35.675 30.675,34.9 30.419,34.644 30.419,34.625 ; CN2.50@32.365,53.48 32.385,53.5 v1(33.3,53.5) ; C58.2@32.525,41.275 v1(32.525,41.95) v1@32.6,42.025 ; C50.2@32.575,33.5 32.575,34 ; v2(33.175,37.15) 33.212,37.187 33.212,37.387 33.445,37.62 33.47,37.62 33.625,37.775 C63.2@33.625,37.8 ; v2@33.25,36.45 33.25,36.483 33.267,36.5 C64.2@33.75,36.5 ; C61.2@33.825,41.275 33.825,41.925 v1@33.9,42 ; v2@34.5,39.05 34.7,38.85 C62.2@35.125,38.85 ; C65.2@34.55,34.05 34.7,33.9 v2(35.125,33.9) ; v2@36.4,37.725 36.487,37.812 36.687,37.812 36.895,38.02 36.895,38.045 37.05,38.2 C68.2@37.075,38.2 ; C66.2@36.5,33.05 36.525,33.05 36.725,33.25 v2@37.05,33.25 ; v2(37.075,32.6) 37.425,32.6 37.625,32.4 C67.2@37.65,32.4 ; v1(43.25,63.355) Q1.2@43.25,64.1 ; C69.2@46.398,60.34 47.11,60.34 v1(47.125,60.325) ; CN6.B12@47.125,9.325 47.25,9.45 CN6.A1@47.25,10.58 ; v1(48.875,32.15) U13.7@51.875,32.15 ; v1(49.575,34.25) U13.10@51.875,34.25 ; v1@49.575,34.275 49.55,34.25 49.55,33.75 49.75,33.55 U13.9@51.875,33.55 ; v1(49.625,38.45) U13.16@51.875,38.45 ; v1(49.625,41.25) U13.20@51.875,41.25 ; CN6.A12@52.75,10.58 52.75,9.45 CN6.B1@52.8,9.4 ; v1(53.25,63.325) C70.1@54.125,63.325 ; LD1.3@54.5,54.875 v1(54.5,56.125) ; v1(56.75,10.75) U15.2@57.775,10.75 ; R45.1@56.825,64.875 v1(57.575,64.875) ; LD2.3@58.25,54.875 v1(58.25,56.125) ; v1(61.5,28.35) C13.1@61.5,29.05 ; CN14.7@62,2.968 v1(62,4.783) ; CN15.3@62,16.885 62.025,16.91 v1(62.025,17.9) ; U14.2@62.9,10.75 v1(63.925,10.75)
  Top Layer w0.3: v1(55.875,25.5) B3.4@58.05,25.5 ; B1.7@61.098,38.902 62.172,39.975 v1(62.175,39.975) ; v1(64.8,25.5) B3.3@66.95,25.5 ; B1.5@65.942,38.442 66.893,39.393 v1(66.9,39.393) ; B1.8@66.402,33.598 v1@67.462,34.659
  Top Layer w0.4: C4.1@3.6,47.4 4.45,47.4 v1(4.475,47.375) ; CN3.3@4,60.25 v1(4,62.125) ; C5.1@22.65,47.35 v1(23.55,47.35) ; C11.1@33.25,48.8 v1(33.95,48.8) ; C6.1@34.05,47.35 v1(35,47.35) ; CN13.4@38,64.25 v1(38,67.125)
  Top Layer w0.5: v1@0.75,16.425 0.775,16.4 v1(0.8,16.4) 1.76,16.4 1.885,16.275 CN1.1@1.885,16.21 ; C7.1@2.8,20.9 v1(3.475,20.9) ; v1@3.525,20.9 4.2,20.9 4.425,20.675 CN1.6@4.425,19.21 ; C2.1@3.6,22.35 v1(4.575,22.35) ; CN4.3@4,2.55 v1(5.475,2.55) ; CN1.7@5.695,16.21 5.695,14.83 v1(5.7,14.825) ; CN1.14@9.505,19.186 CN1.14@9.505,19.21 v1@9.505,20.741 ; v1@12.045,14.854 CN1.17@12.045,16.21 CN1.17@12.045,16.234 ; CN1.22@14.585,19.21 14.585,20.935 14.8,21.15 C1.2@14.8,21.4 14.8,22.573 14.775,22.598 v1(14.775,22.625) ; v1(16.2,0.8) v1(18.4,0.8) ; v1@17.125,14.854 v1@17.125,14.875 ; CN1.25@17.125,16.234 CN1.25@17.125,16.21 v1@17.125,14.875 ; CN1.28@18.395,19.186 CN1.28@18.395,19.21 18.395,22.32 v1(19.3,23.225) ; CN1.31@20.935,16.21 20.935,14.71 20.512,14.287 17.713,14.287 v1@17.125,14.875 ; v1(22.2,22.7) 22.205,22.695 CN1.34@22.205,19.21 CN1.34@22.205,19.186 ; CN1.37@24.745,16.21 24.745,14.88 v1(24.75,14.875) ; CN1.40@26.015,19.21 26.015,20.765 v1(26.025,20.775) ; v1(29.725,22.35) C3.1@30.7,22.35 ; v1(29.825,17.775) CN1.46@29.825,19.21 ; v1(30.18,7.375) U17.2@30.875,7.375 ; 30.475,0.75 30.5,0.775 30.5,0.8 LD4.2@30.5,1.75 ; v1(30.75,20.9) C8.2@31.5,20.9 ; CN1.49@32.365,16.21 32.365,14.81 v1(32.375,14.8) ; 33,0.825 33.025,0.8 ; C35.2@45.5,13.55 v1(45.5,14.18) ; U7.2@46.75,13.875 v1(46.75,14.57) ; v1(60.2,0.8) 60.73,0.8 CN14.5@60.73,2.968
  Top Layer w0.6: v1(0.8,0.8) v1(5.2,0.8) v1(7.4,0.8) v1(16.2,0.8) ; v1(0.8,5.4) v1(0.8,7.6) v1(0.8,14.2) v1(0.8,16.4) v1(0.8,23) v1(0.8,25.2) v1(0.8,34) v1(0.8,36.2) v1(0.8,42.8) v1(0.8,45) v1(0.8,51.8) v1(0.8,54) v1(0.8,58.5) ; v1(0.8,62.5) v1(0.8,64.8) v1(0.8,67) v1(0.8,69.2) v1(5.2,69.2) v1(7.4,69.2) v1(16.2,69.2) v1(18.4,69.2) v1(27.2,69.2) v1(29.4,69.2) v1(40.4,69.2) v1(42.6,69.2) v1(51.4,69.2) v1(53.6,69.2) v1(62.6,69.2) v1(64.8,69.2) v1(69.2,69.2) v1(69.2,64.8) v1(69.2,62.6) v1(69.2,53.8) v1(69.2,51.6) v1(69.2,42.8) v1(69.2,40.6) v1(69.2,29.6) v1(69.2,27.4) v1(69.2,18.6) v1(69.2,16.4) v1(69.2,7.4) v1(69.2,5.2) v1(69.2,3) v1(69.2,0.8) v1(64.8,0.8) v1(62.6,0.8) v1(53.6,0.8) v1(51.4,0.8) v1(42.6,0.8) v1(40.4,0.8) 30.5,0.8 v1(29.4,0.8) v1(27.2,0.8) v1(18.4,0.8)
  Signal Layer 1 w0.6: v1(0.8,0.8) v1(5.2,0.8) v1(7.4,0.8) v1(16.2,0.8) v1(18.4,0.8) v1(27.2,0.8) v1(29.4,0.8) v1(40.4,0.8) v1(42.6,0.8) v1(51.4,0.8) v1(53.6,0.8) v1(62.6,0.8) v1(64.8,0.8) v1(69.2,0.8) v1(69.2,5.2) v1(69.2,7.4) v1(69.2,16.4) v1(69.2,18.6) v1(69.2,27.4) v1(69.2,29.6) v1(69.2,40.6) v1(69.2,42.8) v1(69.2,51.6) v1(69.2,53.8) v1(69.2,62.6) v1(69.2,64.8) v1(69.2,69.2) v1(64.8,69.2) v1(62.6,69.2) v1(53.6,69.2) v1(51.4,69.2) v1(42.6,69.2) v1(40.4,69.2) v1(29.4,69.2) v1(27.2,69.2) v1(18.4,69.2) v1(16.2,69.2) v1(7.4,69.2) v1(5.2,69.2) v1(0.8,69.2) v1(0.8,67) v1(0.8,64.8) v1(0.8,62.5) v1(0.8,58.5) v1(0.8,56.2) v1(0.8,54) v1(0.8,51.8) v1(0.8,45) v1(0.8,42.8) v1(0.8,36.2) v1(0.8,34) v1(0.8,25.2) v1(0.8,23) v1(0.8,16.4) v1(0.8,14.2) v1(0.8,7.6) v1(0.8,5.4) v1(0.8,0.8)
  Signal Layer 2 w0.6: v1(0.8,0.8) v1(5.2,0.8) v1(7.4,0.8) v1(16.2,0.8) v1(18.4,0.8) v1(27.2,0.8) v1(29.4,0.8) v1(40.4,0.8) v1(42.6,0.8) v1(51.4,0.8) v1(53.6,0.8) v1(62.6,0.8) v1(64.8,0.8) v1(69.2,0.8) v1(69.2,5.2) v1(69.2,7.4) v1(69.2,16.4) v1(69.2,18.6) v1(69.2,27.4) v1(69.2,29.6) v1(69.2,40.6) v1(69.2,42.8) v1(69.2,51.6) v1(69.2,53.8) v1(69.2,62.6) v1(69.2,64.8) v1(69.2,69.2) v1(64.8,69.2) v1(62.6,69.2) v1(53.6,69.2) v1(51.4,69.2) v1(42.6,69.2) v1(40.4,69.2) v1(29.4,69.2) v1(27.2,69.2) v1(18.4,69.2) v1(16.2,69.2) v1(7.4,69.2) v1(5.2,69.2) v1(0.8,69.2) v1(0.8,67) v1(0.8,64.8) v1(0.8,62.5) v1(0.8,58.5) v1(0.8,56.2) v1(0.8,54) v1(0.8,51.8) v1(0.8,45) v1(0.8,42.8) v1(0.8,36.2) v1(0.8,34) v1(0.8,25.2) v1(0.8,23) v1(0.8,16.4) v1(0.8,14.2) v1(0.8,7.6) v1(0.8,5.4) v1(0.8,0.8)
  Bottom Layer w0.15: v2(29.275,36.5) U6.H12@29.6,36.175 ; v2(29.275,37.15) U6.G12@29.6,36.825 ; v2(29.275,37.8) U6.F12@29.6,37.475 ; U6.K10@30.9,34.875 v2(31.225,35.2) ; U6.F10@30.9,37.475 v2(31.225,37.15) ; v2(31.225,33.25) U6.M9@31.55,33.575 ; U6.D9@31.55,38.775 v2(31.875,39.1) ; v2(31.875,33.25) U6.M8@32.2,33.575 ; U6.D8@32.2,38.775 v2(32.525,39.1) ; U6.D7@32.85,38.775 v2(33.175,39.1) ; U6.K6@33.5,34.875 v2(33.175,35.2) ; U6.F6@33.5,37.475 v2(33.175,37.15) ; U6.D6@33.5,38.775 v2(33.825,39.1) ; U6.D5@34.15,38.775 v2(34.475,39.1) ; U6.L4@34.8,34.225 v2(35.125,33.9) ; U6.G2@36.1,36.825 v2(36.425,37.15) ; U6.F2@36.1,37.475 v2(36.425,37.8) ; U6.N1@36.75,32.925 v2(37.075,32.6) ; U6.M1@36.75,33.575 v2(37.075,33.25) ; v2(31.225,35.2) U6.J9@31.55,35.525 ; v2(31.225,35.2) U6.K9@31.55,34.875 v2(31.875,35.2) ; v2(31.225,35.2) U6.J10@30.9,35.525 v2(31.225,35.85) ; v2(31.225,35.85) U6.H10@30.9,36.175 v2(31.225,36.5) ; v2(31.225,35.85) U6.H9@31.55,36.175 ; v2(31.225,35.85) U6.J9@31.55,35.525 ; v2(31.225,36.5) U6.G10@30.9,36.825 v2(31.225,37.15) ; v2(31.225,36.5) U6.G9@31.55,36.825 ; v2(31.225,36.5) U6.H9@31.55,36.175 ; v2(31.225,37.15) U6.F9@31.55,37.475 v2(31.875,37.15) ; v2(31.225,37.15) U6.G9@31.55,36.825 ; U6.J9@31.55,35.525 v2(31.875,35.2) ; U6.J9@31.55,35.525 v2(31.875,35.85) ; U6.H9@31.55,36.175 v2(31.875,36.5) ; U6.H9@31.55,36.175 v2(31.875,35.85) ; U6.G9@31.55,36.825 v2(31.875,36.5) ; U6.G9@31.55,36.825 v2(31.875,37.15) ; v2(31.875,35.2) U6.J8@32.2,35.525 ; v2(31.875,35.2) U6.K8@32.2,34.875 v2(32.525,35.2) ; v2(31.875,35.85) U6.H8@32.2,36.175 ; v2(31.875,35.85) U6.J8@32.2,35.525 ; v2(31.875,36.5) U6.H8@32.2,36.175 ; v2(31.875,36.5) U6.G8@32.2,36.825 ; v2(31.875,37.15) U6.F8@32.2,37.475 v2(32.525,37.15) ; v2(31.875,37.15) U6.G8@32.2,36.825 ; U6.J8@32.2,35.525 v2(32.525,35.85) ; U6.J8@32.2,35.525 v2(32.525,35.2) ; U6.H8@32.2,36.175 v2(32.525,35.85) ; U6.H8@32.2,36.175 v2(32.525,36.5) ; U6.G8@32.2,36.825 v2(32.525,37.15) ; U6.G8@32.2,36.825 v2(32.525,36.5) ; v2(32.525,35.2) U6.J7@32.85,35.525 ; v2(32.525,35.2) U6.K7@32.85,34.875 v2(33.175,35.2) ; v2(32.525,35.85) U6.J7@32.85,35.525 ; v2(32.525,35.85) U6.H7@32.85,36.175 ; v2(32.525,36.5) U6.H7@32.85,36.175 ; v2(32.525,36.5) U6.G7@32.85,36.825 ; v2(32.525,37.15) U6.G7@32.85,36.825 ; v2(32.525,37.15) U6.F7@32.85,37.475 v2(33.175,37.15) ; U6.J7@32.85,35.525 v2(33.175,35.2) ; U6.J7@32.85,35.525 v2(33.175,35.85) ; U6.H7@32.85,36.175 v2(33.175,35.85) ; U6.H7@32.85,36.175 v2(33.175,36.5) ; U6.G7@32.85,36.825 v2(33.175,37.15) ; U6.G7@32.85,36.825 v2(33.175,36.5) ; v2(33.175,35.2) U6.J6@33.5,35.525 v2(33.175,35.85) ; v2(33.175,35.85) U6.H6@33.5,36.175 v2(33.175,36.5) ; v2(33.175,36.5) U6.G6@33.5,36.825 v2(33.175,37.15)
  Bottom Layer w0.2: v1(2.5,59.585) 2.542,59.542 3.133,59.542 C33.1@3.175,59.5 C34.2@3.175,58.625 ; v1(3.75,39.25) C24.1@4.55,39.25 ; v1(3.75,45.55) 3.755,45.545 C32.1@3.755,44.875 ; v1(3.775,41.95) C18.1@4.425,41.95 ; C18.1@4.5,41.95 C19.1@5.5,41.95 ; C28.1@4.63,44.875 4.71,44.955 v1(4.71,45.55) ; C19.1@5.525,41.875 6.375,41.875 6.5,41.75 U4.13@7.075,41.75 7.95,41.75 U4.33@8.25,41.45 ; v1(5.75,46.115) 5.755,46.11 C31.1@5.755,45.375 ; R53.2@7.005,48.375 8.775,48.375 9.25,47.9 v1(9.25,47.375) C27.2@9.25,46.7 ; U4.7@8.25,39.075 U4.33@8.25,40.15 ; v1(9.25,35.825) C20.1@9.25,36.55 ; v1(10.25,35.825) R49.2@10.25,36.55 ; C30.1@10.25,46.7 v1(10.25,47.375) ; U4.33@10.825,41.5 11.075,41.75 U4.28@11.925,41.75 12.85,41.75 13.05,41.55 C17.1@13.5,41.55 C16.1@14.5,41.55 v1(14.5,40.85) ; C29.1@11.25,46.7 v1(11.25,47.375) ; R55.2@12.25,46.7 v1(12.25,47.375) ; C22.2@13.25,46.7 v1(13.25,47.375) ; v1(15.5,40.85) C82.1@15.5,41.55 ; v1(17.075,38.725) 17.1,38.75 C85.1@17.8,38.75 ; U19.2@17.75,40.15 17.75,39.325 17.8,39.275 C85.1@17.8,38.85 ; v1(20,41.125) C86.1@20,41.8 ; C80.1@23.25,34.55 23.325,34.475 v1(24.275,34.475) C42.1@24.95,34.475 ; C36.1@23.425,39.65 v1(23.425,40.325) ; v1(24.275,35.525) R25.2@24.95,35.525 ; v1(24.275,38.475) C49.1@24.95,38.475 ; v1(30.275,28.075) C48.1@30.275,28.75 ; v1(31.225,30.4) 31.225,29.975 31.425,29.775 C38.2@32.35,29.775 ; v1(31.675,27.15) R15.2@32.35,27.15 ; v1(33.995,27.15) R11.2@34.67,27.15 ; v1(33.995,29.775) C37.2@34.67,29.775 ; v1(36.275,15.425) C45.1@36.95,15.425 ; v1(36.275,16.4) R34.1@36.95,16.4 ; v1(36.275,17.5) C44.1@36.95,17.5 ; v1(36.5,23.1) C46.1@36.5,23.775 ; v1(37.75,19.55) R40.1@37.75,20.42 ; C40.1@38.48,35.125 v1(39.275,35.125) ; C39.2@38.48,37.725 v1(38.48,38.4) ; X1.4@39.5,37.45 39.505,37.455 v1(39.505,38.3) ; v1(40.55,35.255) X1.2@40.55,36.1 ; v1@41.05,15.4 41.1,15.45 R33.2@42.005,15.45 ; v1(41.05,15.43) U9.8@41.05,16 ; v1(42.35,20.35) 42.355,20.345 C43.1@42.355,19.575 ; v1@43.725,23.275 v1@43.8,23.2 ; v1(43.8,23.25) 43.805,23.245 R30.2@43.805,22.225 ; v1(48.875,32.15) C75.2@51.875,32.15 ; v1@49.6,34.25 50.5,34.25 50.8,34.55 C74.2@51.875,34.55 ; v1@49.625,38.425 50.3,37.75 R46.1@51.875,37.75 ; C76.2@51.875,43.275 v1(51.875,44.55) ; R47.1@64.54,2.518 64.54,1.835 64.8,1.575 v1(64.8,0.8) v1@64.8,0.7
  Bottom Layer w0.3: C15.1@9.45,20 9.45,20.605 9.55,20.705 v1@9.55,20.775 ; v1(14.025,26.2) C77.2@15,26.2 ; C79.2@20,25.95 v1(20,26.625) ; v1(37.675,28.22) R23.2@37.675,28.875 ; v1(39.825,28.22) R27.2@39.825,28.875 ; v1(40.925,32.02) C41.1@40.925,32.675 ; U3.2@57.5,24.062 58.713,24.062 58.824,23.951 59.25,23.525 v1@59.25,22.725 ; SB1.2@59.25,21.6 v1(59.25,22.7)
  Bottom Layer w0.4: v1(43.85,62.2) 43.858,62.192 CN8.7@43.858,60.73 ; v1(47,27.75) C73.2@47,29.075
  Bottom Layer w0.5: C81.1@14.25,32.2 v1(14.25,33) ; v1(17.13,14.849) 18.23,14.849 18.25,14.829 C83.1@18.25,14.825 ; C78.2@18.13,28.555 18.2,28.625 C78.2@18.2,28.75 v1(19.025,28.75) ; U20.1@21.675,21.3 21.7,21.3 22.2,21.8 v1(22.2,22.7) ; C84.1@23.5,20.95 v1(23.5,21.75) ; v1(38.88,23.725) U10.2@39.95,23.725 ; C47.1@41.9,23.275 v1@43.725,23.275 ; C59.1@42.005,45.65 v1(42.975,45.65)
  Bottom Layer w0.6: v1(39.1,42.625) U11.2@40.305,42.625 v1(41.375,42.625) ; C60.1@41.705,39.75 v1(42.525,39.75) ; v1(0.8,0.8) v1(5.2,0.8) v1(7.4,0.8) v1(16.2,0.8) v1(18.4,0.8) v1(27.2,0.8) v1(29.4,0.8) v1(40.4,0.8) v1(42.6,0.8) v1(51.4,0.8) v1(53.6,0.8) v1(62.6,0.8) v1(64.8,0.8) v1(69.2,0.8) v1(69.2,5.2) v1(69.2,7.4) v1(69.2,16.4) v1(69.2,18.6) v1(69.2,27.4) v1(69.2,29.6) v1(69.2,40.6) v1(69.2,42.8) v1(69.2,51.6) v1(69.2,53.8) v1(69.2,62.6) v1(69.2,64.8) v1(69.2,69.2) v1(64.8,69.2) v1(62.6,69.2) v1(53.6,69.2) v1(51.4,69.2) v1(42.6,69.2) v1(40.4,69.2) v1(29.4,69.2) v1(27.2,69.2) v1(18.4,69.2) v1(16.2,69.2) v1(7.4,69.2) v1(5.2,69.2) v1(0.8,69.2) v1(0.8,67) v1(0.8,64.8) v1(0.8,62.5) v1(0.8,58.5) v1(0.8,56.2) v1(0.8,54) v1(0.8,51.8) v1(0.8,45) v1(0.8,42.8) v1(0.8,36.2) v1(0.8,34) v1(0.8,25.2) v1(0.8,23) v1(0.8,16.4) v1(0.8,14.2) v1(0.8,7.6) v1(0.8,5.4) v1(0.8,0.8)
  Bottom Layer w0.8: v1(21.05,29.375) U18.1@21.05,30.825 ; CN9.7@27.094,9.267 27.094,7.756 v1(27.1,7.75) ; CN9.6@29.634,12.472 29.634,10.966 v1(29.65,10.95)
  other v1: 3,0.8 9.6,0.8 11.8,0.8 14,0.8 20.6,0.8 22.8,0.8 25,0.8 31.6,0.8 33.8,0.8 36,0.8 38.2,0.8 44.8,0.8 47,0.8 49.2,0.8 55.8,0.8 58,0.8 67,0.8 0.8,9.8 69.2,9.8 0.8,12 51.75,12 69.2,12 51.75,13.75 49.025,14.125 69.2,14.2 12.05,14.849 47.5,16.25 40.15,16.75 46.4,17.6 49.75,17.75 0.8,18.6 54.35,18.6 40.25,20.5 9.515,20.751 0.8,20.8 69.2,20.8 35.75,21.25 69.2,23 28,23.75 30.25,24.75 34.25,24.75 69.2,25.2 27,26.25 29,26.25 0.8,27.4 26.5,28.25 0.8,29.6 0.8,31.8 69.2,31.8 69.2,34 67.491,34.659 69.2,36.2 31.225,38.175 0.8,38.4 69.2,38.4 8.25,40.25 9.5,40.25 10.75,40.25 0.8,40.6 8.25,41.5 9.5,41.5 10.75,41.5 33.825,41.95 8.25,42.75 9.5,42.75 10.75,42.75 69.2,45 0.8,47.2 69.2,47.2 0.8,49.4 69.2,49.4 17.136,54.82 69.2,56 69.2,58.2 69.2,60.4 69.2,67 3,69.2 9.6,69.2 11.8,69.2 14,69.2 20.6,69.2 22.8,69.2 25,69.2 31.6,69.2 33.8,69.2 36,69.2 38.2,69.2 44.8,69.2 47,69.2 49.2,69.2 55.8,69.2 58,69.2 60.2,69.2 67,69.2
GNDDetect: CN14.11 R47.2 | length 4
  Top Layer w0.12: v1(64,5) 64.505,4.495 64.505,3.003 CN14.11@64.54,2.968
  Bottom Layer w0.12: v1@64.025,4.975 64.34,4.66 64.34,4.654 64.54,4.454 R47.2@64.54,3.418
GPIO30: CN2.10
GPIO32: CN2.12
GPIO38: CN2.22
GPIO40: CN2.24
GPIO43: CN2.28
GPIO45: CN2.30
GPIO46: CN2.34
GPIO51: CN2.40
GPIO53: CN2.42
JNTRST: CN15.9 SB9.2 U15.4 | length 87.4
  Top Layer w0.12: v1(15,37.15) 15,38.925 15.63,39.555 20.105,39.555 22.6,42.05 22.6,43.071 26.755,47.226 26.755,48.415 27.145,48.805 28.945,48.805 31.875,45.875 v1(35.25,45.875) ; v1(36.1,41.875) 36.1,41.225 38,39.325 38,34.4 40.35,32.05 40.35,28.066 40.691,27.725 43.011,27.725 44.31,26.426 44.31,22.065 53.8,12.575 58.1,12.575 58.675,12 58.675,10.5 58.935,10.24 59.075,10.1 U15.4@59.475,10.1 59.476,10.101 60.201,10.101 60.69,10.59 60.69,11.329 63.275,13.914 63.275,16.1
  Bottom Layer w0.12: v1(15,37.15) 15,37.975 15.05,38.025 ; v1(35.25,45.875) 35.6,45.525 35.6,43.086 36.1,42.586 v1(36.1,41.875)
LEDU: Q1.1 R42.2 SB2.2 | length 5.8
  Top Layer w0.2: v1(41.35,64.1) Q1.1@42.25,64.1 42.25,62.925 R42.2@42.3,62.875
  Bottom Layer w0.2: v1(41.35,64.1) 43.35,64.1 43.95,63.5 44.75,63.5
MCU.CTS: SB5.1 U6.N13 | length 3.8
  Bottom Layer w0.12: 25.275,33.275 26.275,33.275 26.3,33.25 28.625,33.25 U6.N13@28.95,32.925
MCU.RTS: SB10.1 U6.N14 | length 3.4
  Bottom Layer w0.12: 25.5,31.925 25.675,31.75 26.1,31.75 26.5,32.15 26.525,32.15 27,32.625 27.519,32.625 27.524,32.62 27.995,32.62 U6.N14@28.3,32.925
MCU.SWCLK: CN1.15 CN14.6 CN14.9 CN15.4 R18.2 U14.1 | length 136.8
  Top Layer w0.12: v1(10.775,14.825) CN1.15@10.775,16.21 10.775,17.225 11.035,17.485 18.485,17.485 19.025,18.025 19.025,21.4 20.125,22.5 20.125,23.55 v1@21.65,25.075 ; v1(25.662,25.213) 25.657,25.213 25.32,25.55 25.32,29.17 25.322,29.172 25.322,29.953 25.47,30.102 25.47,33.781 25.715,34.026 25.715,39.454 27.185,40.924 27.185,42.36 29.48,44.655 30.45,44.655 v1(30.9,44.205) ; v1(56.75,13.875) 56.763,13.887 v1(61.113,13.887) ; v1(62.8,12.2) 62.8,11.5 U14.1@62.9,11.4 ; U14.1@62.85,11.425 61.65,11.425 61.25,11.025 61.25,9.375 60.73,8.855 CN14.6@60.73,7.032 60.764,6.998 60.764,5.511 60.95,5.325 62.5,5.325 63.27,4.555 CN14.9@63.27,2.968
  Top Layer w0.2: CN15.4@60.725,16.885 v1(60.725,17.9)
  Bottom Layer w0.12: v1(10.775,14.825) 10.775,11.55 11.415,10.91 14.501,10.91 14.651,10.76 18.056,10.76 18.253,10.957 20.322,10.957 20.849,10.43 22.119,10.43 22.459,10.77 25.324,10.77 26.255,11.701 26.255,13.655 28.27,15.67 31.58,15.67 31.875,15.375 31.875,12.518 36.318,8.075 38.625,8.075 39.38,7.32 40.876,7.32 41.201,6.995 44.701,6.995 45.361,6.335 45.701,6.335 45.706,6.33 49.69,6.33 49.695,6.335 54.992,6.335 55.665,7.008 55.665,11.808 56.75,12.893 v1(56.75,13.875) ; v1(21.675,25.1) 23.35,25.1 23.45,25.2 v1@25.625,25.2 ; R18.2@30.9,43.5 v1(30.9,44.205) ; v1(60.725,17.9) 60.725,14.275 v1(62.8,12.2)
